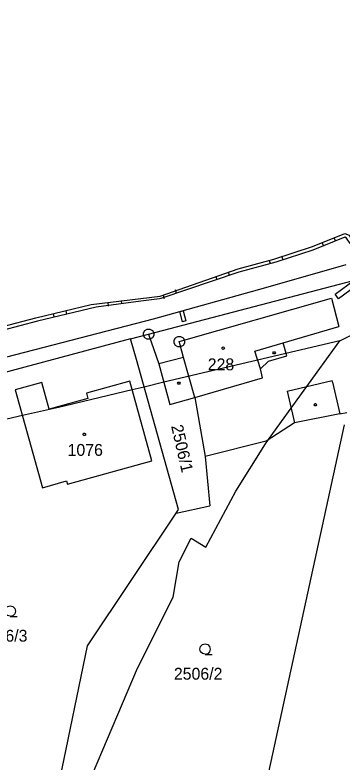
# Model space of a CAD drawing. Extents: x -760611 to -758411, y -1176479 to -1174807.
# Drawn here: x -759278.5 to -759231.6, y -1175131 to -1175024.1 of the extents above; entities that cross this region are included whole.
import ezdxf

# ---------------------------------------------------------------- set-up
doc = ezdxf.new("R2010")
doc.units = 0
for name, color, linetype in [('1', 7, 'Continuous'), ('11', 7, 'Continuous'), ('12', 7, 'Continuous'), ('13', 7, 'Continuous'), ('2', 7, 'Continuous'), ('3', 7, 'Continuous'), ('4', 7, 'Continuous'), ('5', 7, 'Continuous'), ('8', 7, 'Continuous')]:
    doc.layers.add(name, color=color, linetype=linetype)

msp = doc.modelspace()

# ---------------------------------------------------------------- linework, layer by layer
at = {"layer": '1'}
for p, q in [((-759231.08, -1175059.85), (-759242.58, -1175063.11)), ((-759259.32, -1175069.76), (-759226.61, -1175061.18)), ((-759242.58, -1175063.11), (-759258.67, -1175067.6)), ((-759258.67, -1175067.6), (-759282.82, -1175073.86)), ((-759261.9, -1175070.45), (-759259.32, -1175069.76)), ((-759259.32, -1175069.76), (-759257.84, -1175074.01)), ((-759261.9, -1175070.45), (-759284.49, -1175076.48)), ((-759261.07, -1175073.38), (-759261.9, -1175070.45)), ((-759255.03, -1175094.84), (-759261.07, -1175073.38)), ((-759257.84, -1175074.01), (-759256.28, -1175079.83)), ((-759262.04, -1175076.5), (-759268.23, -1175078.21)), ((-759258.88, -1175087.89), (-759262.04, -1175076.5)), ((-759274.61, -1175076.69), (-759278.42, -1175077.74)), ((-759273.59, -1175080.49), (-759274.61, -1175076.69)), ((-759278.42, -1175077.74), (-759274.54, -1175091.72)), ((-759268.23, -1175078.21), (-759268.03, -1175078.95)), ((-759268.03, -1175078.95), (-759273.59, -1175080.49)), ((-759256.28, -1175079.83), (-759252.69, -1175078.8)), ((-759252.69, -1175078.8), (-759251.21, -1175087.25)), ((-759231.94, -1175081.17), (-759238.44, -1175082.44)), ((-759231.94, -1175081.17), (-759230.92, -1175080.96)), ((-759231.31, -1175082.74), (-759244.42, -1175142.81)), ((-759238.44, -1175082.44), (-759242.49, -1175085.07)), ((-759242.49, -1175085.07), (-759251.21, -1175087.25)), ((-759251.21, -1175087.25), (-759250.54, -1175094.34)), ((-759270.94, -1175091.24), (-759258.88, -1175087.89)), ((-759274.54, -1175091.72), (-759271.07, -1175090.76)), ((-759271.07, -1175090.76), (-759270.94, -1175091.24)), ((-759255.4, -1175095.39), (-759250.54, -1175094.34)), ((-759268.08, -1175114.33), (-759255.4, -1175095.39)), ((-759255.4, -1175095.39), (-759255.03, -1175094.84)), ((-759278.28, -1175163.97), (-759268.08, -1175114.33))]:
    msp.add_line(p, q, dxfattribs=at)
at = {"layer": '11'}
for points in [[(-759231.94, -1175070.7), (-759228.29, -1175068.9), (-759208.26, -1175059.02), (-759208.14, -1175058.96), (-759207.28, -1175058.54), (-759203.05, -1175056.46), (-759194.46, -1175051.13), (-759180.78, -1175042.66), (-759174.58, -1175038.82), (-759172.73, -1175036.94), (-759166.25, -1175030.34), (-759160.11, -1175024.09)], [(-759231.94, -1175070.7), (-759257.13, -1175076.65), (-759259.96, -1175077.32), (-759261.7, -1175077.73), (-759272.25, -1175080.23), (-759277.4, -1175081.41), (-759285.99, -1175083.38)], [(-759246.85, -1175092.2), (-759242.59, -1175085.45), (-759242.15, -1175084.85), (-759231.94, -1175070.7)], [(-759302.17, -1175262.03), (-759302.03, -1175261.55), (-759299.47, -1175252.11), (-759298.73, -1175249.35), (-759297.4, -1175234.13), (-759293.92, -1175210.45), (-759292.63, -1175205.38), (-759291.77, -1175202), (-759288.78, -1175195.24), (-759288.34, -1175191.86), (-759285.77, -1175185.1), (-759279.57, -1175164.75), (-759276.09, -1175153.33), (-759274.19, -1175147.08), (-759269.92, -1175137.79), (-759267.35, -1175132.72), (-759260.94, -1175117.52), (-759255.81, -1175107.39), (-759254.95, -1175102.32), (-759253.24, -1175098.94), (-759251.12, -1175100.22), (-759246.85, -1175092.2)]]:
    msp.add_lwpolyline(points, dxfattribs=at)
at = {"layer": '12'}
for p, q in [((-759254.93, -1175070.83), (-759233.14, -1175064.6)), ((-759233.14, -1175064.6), (-759232.1, -1175068.65)), ((-759240.05, -1175070.99), (-759232.1, -1175068.65)), ((-759254.8, -1175071.3), (-759254.93, -1175070.83)), ((-759244.14, -1175072.19), (-759240.05, -1175070.99)), ((-759254.32, -1175073.08), (-759254.8, -1175071.3)), ((-759243.32, -1175074.73), (-759244.14, -1175072.19)), ((-759252.69, -1175078.8), (-759254.32, -1175073.08)), ((-759243.01, -1175076.01), (-759243.32, -1175074.73)), ((-759262.04, -1175076.5), (-759268.23, -1175078.21)), ((-759258.88, -1175087.89), (-759262.04, -1175076.5)), ((-759252.69, -1175078.8), (-759243.01, -1175076.01)), ((-759274.61, -1175076.69), (-759278.42, -1175077.74)), ((-759273.59, -1175080.49), (-759274.61, -1175076.69)), ((-759278.42, -1175077.74), (-759274.54, -1175091.72)), ((-759268.23, -1175078.21), (-759268.03, -1175078.95)), ((-759268.03, -1175078.95), (-759273.59, -1175080.49)), ((-759270.94, -1175091.24), (-759258.88, -1175087.89)), ((-759274.54, -1175091.72), (-759271.07, -1175090.76)), ((-759271.07, -1175090.76), (-759270.94, -1175091.24))]:
    msp.add_line(p, q, dxfattribs=at)
at = {"layer": '13'}
for p, q in [((-759232.55, -1175056.43), (-759232.74, -1175055.97)), ((-759234.47, -1175056.68), (-759234.28, -1175057.15)), ((-759242.06, -1175059.19), (-759241.93, -1175059.68)), ((-759240.08, -1175059.12), (-759240.23, -1175058.65)), ((-759249.71, -1175061.52), (-759249.54, -1175061.99)), ((-759247.75, -1175061.36), (-759247.91, -1175060.89)), ((-759255.34, -1175063.91), (-759255.5, -1175063.44)), ((-759257.26, -1175064.17), (-759257.09, -1175064.64)), ((-759265.18, -1175065.23), (-759265.12, -1175065.73)), ((-759263.16, -1175065.42), (-759263.23, -1175064.92)), ((-759273.01, -1175066.82), (-759272.89, -1175067.3)), ((-759271.02, -1175066.9), (-759271.13, -1175066.41))]:
    msp.add_line(p, q, dxfattribs=at)
for points in [[(-759280.32, -1175069.22), (-759280.19, -1175068.65), (-759275.46, -1175067.4), (-759267.57, -1175065.52), (-759257.68, -1175064.32), (-759246.5, -1175060.39), (-759241.38, -1175059.01), (-759235.85, -1175057.24), (-759231.22, -1175055.37), (-759230.63, -1175055.61), (-759230.35, -1175056.06), (-759230.48, -1175056.77), (-759230.97, -1175056.01), (-759231.23, -1175055.9), (-759235.83, -1175057.76), (-759241.1, -1175059.45), (-759246.41, -1175060.91), (-759257.6, -1175064.67), (-759257.79, -1175064.7), (-759260.43, -1175065.05), (-759266.85, -1175065.91), (-759275.26, -1175067.9)], [(-759232.14, -1175064.69), (-759232.61, -1175064.04), (-759229.9, -1175062.04), (-759227.81, -1175061.49)], [(-759254.47, -1175068), (-759254.88, -1175066.54), (-759254.39, -1175066.41), (-759253.99, -1175067.86)]]:
    msp.add_lwpolyline(points, close=True, dxfattribs=at)
at = {"layer": '3'}
for points in [[(-759279.13, -1175110.12), (-759279.51, -1175110.02), (-759279.78, -1175109.75), (-759279.88, -1175109.38), (-759279.78, -1175109.01), (-759279.51, -1175108.74), (-759279.14, -1175108.64), (-759278.77, -1175108.74), (-759278.5, -1175109.01), (-759278.4, -1175109.39), (-759278.5, -1175109.77), (-759278.77, -1175110.04), (-759279.15, -1175110.14), (-759278.15, -1175110.14)], [(-759251.23, -1175115.56), (-759251.61, -1175115.46), (-759251.88, -1175115.19), (-759251.98, -1175114.82), (-759251.88, -1175114.45), (-759251.61, -1175114.18), (-759251.24, -1175114.08), (-759250.87, -1175114.18), (-759250.6, -1175114.45), (-759250.5, -1175114.83), (-759250.6, -1175115.21), (-759250.87, -1175115.48), (-759251.25, -1175115.58), (-759250.25, -1175115.58)]]:
    msp.add_lwpolyline(points, dxfattribs=at)
at = {"layer": '4'}
for p, q in [((-759254.93, -1175070.83), (-759233.14, -1175064.6)), ((-759233.14, -1175064.6), (-759232.1, -1175068.65)), ((-759240.05, -1175070.99), (-759232.1, -1175068.65)), ((-759254.8, -1175071.3), (-759254.93, -1175070.83)), ((-759244.14, -1175072.19), (-759240.05, -1175070.99)), ((-759239.54, -1175072.87), (-759240.05, -1175070.99)), ((-759254.32, -1175073.08), (-759254.8, -1175071.3)), ((-759243.32, -1175074.73), (-759244.14, -1175072.19)), ((-759254.32, -1175073.08), (-759257.84, -1175074.01)), ((-759252.69, -1175078.8), (-759254.32, -1175073.08)), ((-759242.15, -1175073.63), (-759239.54, -1175072.87)), ((-759243.32, -1175074.73), (-759242.15, -1175073.63)), ((-759243.01, -1175076.01), (-759243.32, -1175074.73)), ((-759252.69, -1175078.8), (-759243.01, -1175076.01)), ((-759239.49, -1175077.91), (-759233.03, -1175076.41)), ((-759232.99, -1175076.61), (-759233.03, -1175076.41)), ((-759232.99, -1175076.61), (-759231.94, -1175081.17)), ((-759239.49, -1175077.91), (-759238.44, -1175082.44))]:
    msp.add_line(p, q, dxfattribs=at)
at = {"layer": '5'}
for points in [[(-759248.65, -1175071.59), (-759248.55, -1175071.61), (-759248.5, -1175071.7), (-759248.48, -1175071.76), (-759248.5, -1175071.85), (-759248.58, -1175071.92), (-759248.65, -1175071.93), (-759248.74, -1175071.9), (-759248.8, -1175071.84), (-759248.82, -1175071.76), (-759248.8, -1175071.67), (-759248.72, -1175071.6)], [(-759241.26, -1175072.28), (-759241.17, -1175072.43), (-759241.26, -1175072.58), (-759241.44, -1175072.58), (-759241.53, -1175072.43), (-759241.44, -1175072.28)], [(-759254.91, -1175076.63), (-759254.82, -1175076.78), (-759254.91, -1175076.93), (-759255.09, -1175076.93), (-759255.18, -1175076.78), (-759255.09, -1175076.63)], [(-759235.36, -1175079.7), (-759235.27, -1175079.85), (-759235.36, -1175080), (-759235.54, -1175080), (-759235.63, -1175079.85), (-759235.54, -1175079.7)], [(-759268.53, -1175083.93), (-759268.43, -1175083.95), (-759268.38, -1175084.04), (-759268.36, -1175084.1), (-759268.38, -1175084.19), (-759268.46, -1175084.26), (-759268.53, -1175084.27), (-759268.62, -1175084.24), (-759268.68, -1175084.18), (-759268.7, -1175084.1), (-759268.68, -1175084.01), (-759268.6, -1175083.94)]]:
    msp.add_lwpolyline(points, close=True, dxfattribs=at)
at = {"layer": '8'}
for p, q in [((-759259.37, -1175069.76), (-759259.27, -1175069.76)), ((-759254.98, -1175070.83), (-759254.88, -1175070.83))]:
    msp.add_line(p, q, dxfattribs=at)
for points in [[(-759259.13, -1175069.04), (-759258.79, -1175069.23), (-759258.6, -1175069.57), (-759258.6, -1175069.96), (-759258.79, -1175070.3), (-759259.13, -1175070.49), (-759259.52, -1175070.49), (-759259.86, -1175070.3), (-759260.05, -1175069.96), (-759260.05, -1175069.57), (-759259.86, -1175069.23), (-759259.52, -1175069.04)], [(-759254.74, -1175070.11), (-759254.4, -1175070.3), (-759254.21, -1175070.64), (-759254.21, -1175071.03), (-759254.4, -1175071.37), (-759254.74, -1175071.56), (-759255.13, -1175071.56), (-759255.47, -1175071.37), (-759255.66, -1175071.03), (-759255.66, -1175070.64), (-759255.47, -1175070.3), (-759255.13, -1175070.11)]]:
    msp.add_lwpolyline(points, close=True, dxfattribs=at)

# ---------------------------------------------------------------- texts
at = {"layer": '2'}
for s, p in [('228', (-759250.86, -1175074.93)), ('1076', (-759270.93, -1175087.17)), ('2506/3', (-759283.63, -1175113.75)), ('2506/2', (-759255.71, -1175119.19))]:
    msp.add_text(s, height=1.7, dxfattribs=at).set_placement(p)
msp.add_text('2506/1', height=1.7, rotation=282.9266, dxfattribs=at).set_placement((-759256.12, -1175082.9))

doc.saveas('drawing.dxf')
